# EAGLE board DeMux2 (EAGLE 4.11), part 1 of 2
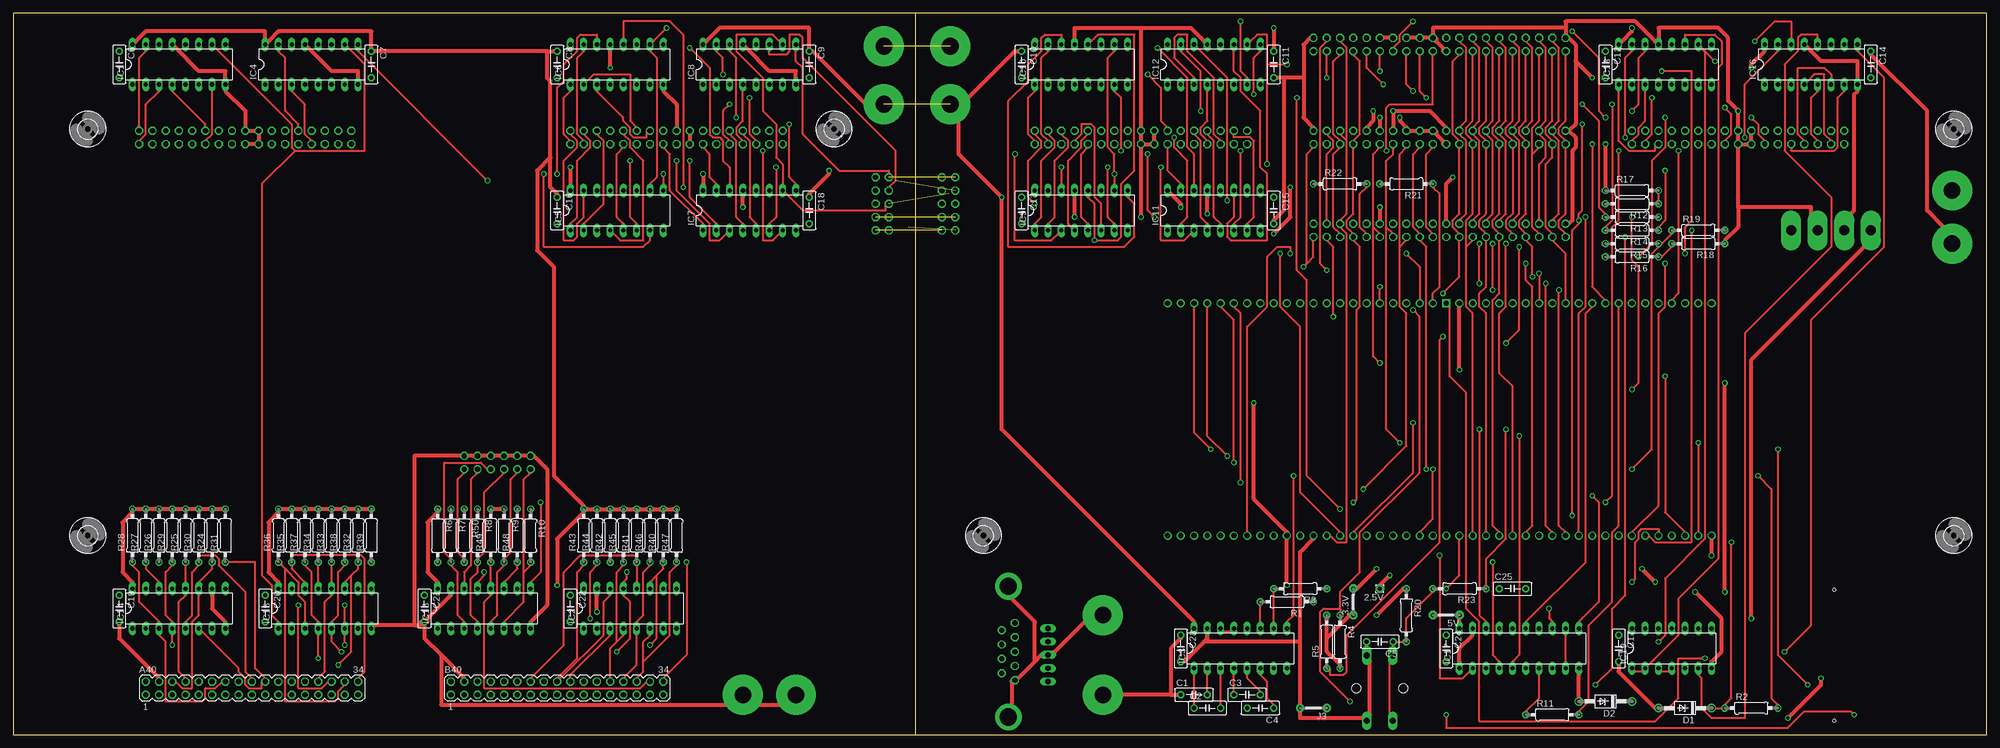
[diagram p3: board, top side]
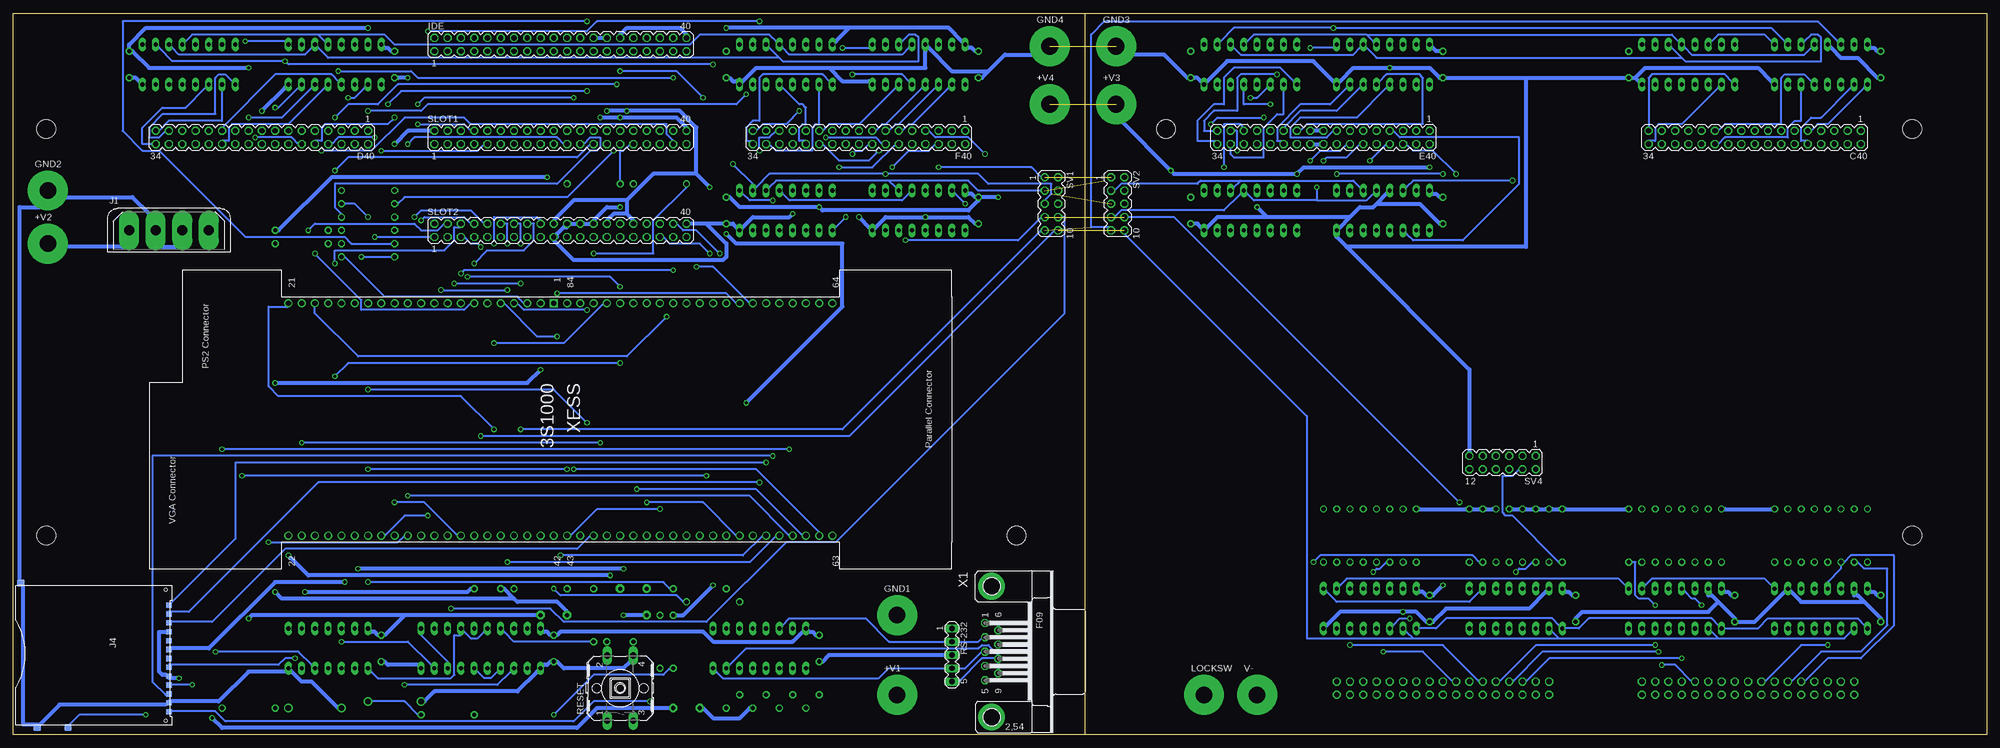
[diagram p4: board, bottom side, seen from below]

Size 377.82 x 138.11 mm. Coordinates in mm from the lower left corner, seen from the top.
Outline: 377.82,138.11 377.82,0 174.62,0 172.72,0
Outline: 377.82,138.11 173.04,138.11
Outline: 173.04,138.11 172.72,138.11
Outline: 172.72,138.11 0,138.11 0,0 172.72,0
Outline: 377.82,138.11 173.04,138.11
Outline: 172.72,138.11 172.72,0
Copper layers (1*16): Top 0.035mm / dielectric 1.5mm / Bottom 0.035mm
Design rules "15mils": minimum track width 15mil, minimum drill 24mil, track to track 15mil, track to pad 10mil, pad to pad 10mil, via to via 10mil, smd to smd 10mil, copper to edge 25mil, drill to drill 10mil, minimum pad ring 10mil, minimum via ring 8mil, stop-mask expansion 0mil, vias tented up to drill 0mil, thermal gap 10mil
Net classes: 1 supply: width 0.762 mm

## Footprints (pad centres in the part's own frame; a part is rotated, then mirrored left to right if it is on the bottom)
1,6/0,8 = drill 0.813 pad 1.6 octagon: 1 0,0
05 = drill 0.813 pad 1.6 octagon: 1 -2.54,0; 2 2.54,0
SPADELUG = drill 3.175 pad 7.62 round: 1 0,0
MA17-2 = drill 1.016 octagon: 1 -20.32,-1.27; 2 -20.32,1.27; 3 -17.78,-1.27; 4 -17.78,1.27; 5 -15.24,-1.27; 6 -15.24,1.27; 7 -12.7,-1.27; 8 -12.7,1.27; 9 -10.16,-1.27; 10 -10.16,1.27; 11 -7.62,-1.27; 12 -7.62,1.27; 13 -5.08,-1.27; 14 -5.08,1.27; 15 -2.54,-1.27; 16 -2.54,1.27; 17 0,-1.27; 18 0,1.27; 19 2.54,-1.27; 20 2.54,1.27; 21 5.08,-1.27; 22 5.08,1.27; 23 7.62,-1.27; 24 7.62,1.27; 25 10.16,-1.27; 26 10.16,1.27; 27 12.7,-1.27; 28 12.7,1.27; 29 15.24,-1.27; 30 15.24,1.27; 31 17.78,-1.27; 32 17.78,1.27; 33 20.32,-1.27; 34 20.32,1.27
C050-025X075 = drill 0.813 octagon: 1 -2.54,0; 2 2.54,0
DO41Z10 = drill 1.118 round: A 5.08,0; C -5.08,0
DIL16 = drill 0.813 long: 1 -8.89,-3.81; 2 -6.35,-3.81; 3 -3.81,-3.81; 4 -1.27,-3.81; 5 1.27,-3.81; 6 3.81,-3.81; 7 6.35,-3.81; 8 8.89,-3.81; 9 8.89,3.81; 10 6.35,3.81; 11 3.81,3.81; 12 1.27,3.81; 13 -1.27,3.81; 14 -3.81,3.81; 15 -6.35,3.81; 16 -8.89,3.81
DIL20 = drill 0.813 long: 1 -11.43,-3.81; 2 -8.89,-3.81; 3 -6.35,-3.81; 4 -3.81,-3.81; 5 -1.27,-3.81; 6 1.27,-3.81; 7 3.81,-3.81; 8 6.35,-3.81; 9 8.89,-3.81; 10 11.43,-3.81; 11 11.43,3.81; 12 8.89,3.81; 13 6.35,3.81; 14 3.81,3.81; 15 1.27,3.81; 16 -1.27,3.81; 17 -3.81,3.81; 18 -6.35,3.81; 19 -8.89,3.81; 20 -11.43,3.81
DIL14 = drill 0.813 long: 1 -7.62,-3.81; 2 -5.08,-3.81; 3 -2.54,-3.81; 4 0,-3.81; 5 2.54,-3.81; 6 5.08,-3.81; 7 7.62,-3.81; 8 7.62,3.81; 9 5.08,3.81; 10 2.54,3.81; 11 0,3.81; 12 -2.54,3.81; 13 -5.08,3.81; 14 -7.62,3.81
MA20-2 = drill 1.016 octagon: 1 -24.13,-1.27; 2 -24.13,1.27; 3 -21.59,-1.27; 4 -21.59,1.27; 5 -19.05,-1.27; 6 -19.05,1.27; 7 -16.51,-1.27; 8 -16.51,1.27; 9 -13.97,-1.27; 10 -13.97,1.27; 11 -11.43,-1.27; 12 -11.43,1.27; 13 -8.89,-1.27; 14 -8.89,1.27; 15 -6.35,-1.27; 16 -6.35,1.27; 17 -3.81,-1.27; 18 -3.81,1.27; 19 -1.27,-1.27; 20 -1.27,1.27; 21 1.27,-1.27; 22 1.27,1.27; 23 3.81,-1.27; 24 3.81,1.27; 25 6.35,-1.27; 26 6.35,1.27; 27 8.89,-1.27; 28 8.89,1.27; 29 11.43,-1.27; 30 11.43,1.27; 31 13.97,-1.27; 32 13.97,1.27; 33 16.51,-1.27; 34 16.51,1.27; 35 19.05,-1.27; 36 19.05,1.27; 37 21.59,-1.27; 38 21.59,1.27; 39 24.13,-1.27; 40 24.13,1.27
FLOPPY-4 = drill 1.93 pad 3.81 long: 1 7.62,0; 2 2.54,0; 3 -2.54,0; 4 -7.62,0
SCDA5A = smd 1 x 1.3: 1 -7.525,-0.65; 2 -5.825,-0.65; 3 -4.125,-0.65; 3A -2.425,-0.65; 4 -0.725,-0.65; 4A 0.975,-0.65; 5 2.675,-0.65; 6 4.375,-0.65; 7 6.075,-0.65; 8 7.775,-0.65; 9 -9.225,-0.65; 10 11.175,-0.65; 11 9.475,-0.65 | smd 1.4 x 1.4: 12 14.2,-19.955; 13 14.2,-25.875; 14 -13.475,-28.975 | hole 0.61: 12.875,-1.235; -12.125,-1.235
0207/10 = drill 0.813 octagon: 1 -5.08,0; 2 5.08,0
B3F-40XX = drill 1.194 long: 1 -6.248,2.489; 2 6.248,2.489; 3 -6.248,-2.489; 4 6.248,-2.489 | hole 1.803: 0,-4.496; 0,4.496
MA05-1 = drill 1.016 long: 1 -5.08,0; 2 -2.54,0; 3 0,0; 4 2.54,0; 5 5.08,0
MA05-2 = drill 1.016 octagon: 1 -5.08,-1.27; 2 -5.08,1.27; 3 -2.54,-1.27; 4 -2.54,1.27; 5 0,-1.27; 6 0,1.27; 7 2.54,-1.27; 8 2.54,1.27; 9 5.08,-1.27; 10 5.08,1.27
MA06-2 = drill 1.016 octagon: 1 -6.35,-1.27; 2 -6.35,1.27; 3 -3.81,-1.27; 4 -3.81,1.27; 5 -1.27,-1.27; 6 -1.27,1.27; 7 1.27,-1.27; 8 1.27,1.27; 9 3.81,-1.27; 10 3.81,1.27; 11 6.35,-1.27; 12 6.35,1.27
3,6 = hole 3.6: 0,0
F09HP = drill 1.016 octagon: 1 -5.486,-1.27; 2 -2.743,-1.27; 3 0,-1.27; 4 2.743,-1.27; 5 5.486,-1.27; 6 -4.115,1.27; 7 -1.372,1.27; 8 1.372,1.27; 9 4.115,1.27 | drill 3.302 pad 5.08 round: G1 -12.522,0; G2 12.522,0
3S1000 = drill 1.016 square: 1 0,0 | drill 1.016 round: 2 0,-2.54; 3 0,-5.08; 4 0,-7.62; 5 0,-10.16; 6 0,-12.7; 7 0,-15.24; 8 0,-17.78; 9 0,-20.32; 10 0,-22.86; 11 0,-25.4; 12 0,-27.94; 13 0,-30.48; 14 0,-33.02; 15 0,-35.56; 16 0,-38.1; 17 0,-40.64; 18 0,-43.18; 19 0,-45.72; 20 0,-48.26; 21 0,-50.8; 22 44.45,-50.8; 23 44.45,-48.26; 24 44.45,-45.72; 25 44.45,-43.18; 26 44.45,-40.64; 27 44.45,-38.1; 28 44.45,-35.56; 29 44.45,-33.02; 30 44.45,-30.48; 31 44.45,-27.94; 32 44.45,-25.4; 33 44.45,-22.86; 34 44.45,-20.32; 35 44.45,-17.78; 36 44.45,-15.24; 37 44.45,-12.7; 38 44.45,-10.16; 39 44.45,-7.62; 40 44.45,-5.08; 41 44.45,-2.54; 42 44.45,0; 43 44.45,2.54; 44 44.45,5.08; 45 44.45,7.62; 46 44.45,10.16; 47 44.45,12.7; 48 44.45,15.24; 49 44.45,17.78; 50 44.45,20.32; 51 44.45,22.86; 52 44.45,25.4; 53 44.45,27.94; 54 44.45,30.48; 55 44.45,33.02; 56 44.45,35.56; 57 44.45,38.1; 58 44.45,40.64; 59 44.45,43.18; 60 44.45,45.72; 61 44.45,48.26; 62 44.45,50.8; 63 44.45,53.34; 64 0,53.34; 65 0,50.8; 66 0,48.26; 67 0,45.72; 68 0,43.18; 69 0,40.64; 70 0,38.1; 71 0,35.56; 72 0,33.02; 73 0,30.48; 74 0,27.94; 75 0,25.4; 76 0,22.86; 77 0,20.32; 78 0,17.78; 79 0,15.24; 80 0,12.7; 81 0,10.16; 82 0,7.62; 83 0,5.08; 84 0,2.54

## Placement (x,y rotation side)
2.5V  [1,6/0,8]  261.62,27.94 180 top
3.3V  J5MM  [05]  256.54,25.4 90 top
5V  J5MM  [05]  274.32,22.86 180 top
+V1  LUG  [SPADELUG]  208.6,7.62 0 bottom
+V2  LUG  [SPADELUG]  371.16,93.98 0 bottom
+V3  LUG  [SPADELUG]  166.69,120.65 0 bottom
+V4  LUG  [SPADELUG]  179.39,120.65 0 bottom
A40  [MA17-2]  45.72,8.89 0 top
B40  [MA17-2]  104.14,8.89 0 top
C1  0.1uf  [C050-025X075]  226.06,7.62 0 top
C2  0.1uf  [C050-025X075]  228.6,5.08 0 top
C3  0.1uf  [C050-025X075]  236.22,7.62 0 top
C4  0.1uf  [C050-025X075]  238.76,5.08 180 top
C5  0.1uf  [C050-025X075]  261.62,17.78 180 top
C6  0.1uf  [C050-025X075]  20.32,128.27 270 top
C7  0.1uf  [C050-025X075]  68.58,128.27 270 top
C8  0.1uf  [C050-025X075]  104.14,128.27 270 top
C9  0.1uf  [C050-025X075]  152.4,128.27 270 top
C10  0.1uf  [C050-025X075]  193.04,128.27 270 top
C11  0.1uf  [C050-025X075]  241.3,128.27 270 top
C12  0.1uf  [C050-025X075]  304.8,128.27 270 top
C13  0.1uf  [C050-025X075]  193.04,100.33 270 top
C14  0.1uf  [C050-025X075]  355.6,128.27 270 top
C15  0.1uf  [C050-025X075]  241.3,100.33 270 top
C16  0.1uf  [C050-025X075]  104.14,100.33 270 top
C17  0.1uf  [C050-025X075]  307.34,16.51 270 top
C18  0.1uf  [C050-025X075]  152.4,100.33 270 top
C19  0.1uf  [C050-025X075]  20.32,24.13 270 top
C20  0.1uf  [C050-025X075]  48.26,24.13 270 top
C21  0.1uf  [C050-025X075]  78.74,24.13 270 top
C22  0.1uf  [C050-025X075]  106.68,24.13 270 top
C23  0.1uf  [C050-025X075]  223.52,16.51 270 top
C24  0.1uf  [C050-025X075]  274.32,16.51 270 top
C25  0.1uf  [C050-025X075]  287.02,27.94 0 top
C40  [MA17-2]  44.45,114.3 180 bottom
D1  1N4728  [DO41Z10]  320.04,5.08 180 top
D2  1N4728  [DO41Z10]  304.8,6.35 180 top
D40  [MA17-2]  330.2,114.3 180 bottom
E40  [MA17-2]  127,114.3 180 bottom
F40  [MA17-2]  215.9,114.3 180 bottom
GND1  LUG  [SPADELUG]  208.6,22.86 0 bottom
GND2  LUG  [SPADELUG]  371.16,104.14 0 bottom
GND3  LUG  [SPADELUG]  166.69,131.76 0 bottom
GND4  LUG  [SPADELUG]  179.39,131.76 0 bottom
IC1  74HC595N  [DIL16]  31.75,128.27 0 top
IC2  74HC165N  [DIL16]  118.11,24.13 0 top
IC3  MAX232  [DIL16]  234.95,16.51 0 top
IC4  74HC595N  [DIL16]  57.15,128.27 0 top
IC5  74HC595N  [DIL16]  115.57,100.33 0 top
IC6  74HC595N  [DIL16]  115.57,128.27 0 top
IC7  74HC595N  [DIL16]  140.97,100.33 0 top
IC8  74HC595N  [DIL16]  140.97,128.27 0 top
IC9  74HC595N  [DIL16]  204.47,100.33 0 top
IC10  74HC595N  [DIL16]  204.47,128.27 0 top
IC11  74HC595N  [DIL16]  229.87,100.33 0 top
IC12  74HC595N  [DIL16]  229.87,128.27 0 top
IC13  74HC595N  [DIL16]  316.23,128.27 0 top
IC14  74HC165N  [DIL16]  31.75,24.13 0 top
IC15  74HC165N  [DIL16]  59.69,24.13 0 top
IC16  74HC595N  [DIL16]  344.17,128.27 0 top
IC17  74HCT244N  [DIL20]  288.29,16.51 0 top
IC18  74HC165N  [DIL16]  90.17,24.13 0 top
IC19  74ALS00N  [DIL14]  317.5,16.51 0 top
IDE  [MA20-2]  273.05,132.08 0 bottom
J1  [FLOPPY-4]  347.98,96.52 0 bottom
J3  J5MM  [05]  248.92,5.08 180 top
J4  SDCARD  [SCDA5A]  347.35,15.56 270 bottom
LOCKSW  LUG  [SPADELUG]  149.86,7.62 0 bottom
R1  330  [0207/10]  243.84,25.4 180 top
R2  330  [0207/10]  332.74,5.08 0 top
R3  330  [0207/10]  246.38,27.94 180 top
R4  330  [0207/10]  254,17.78 270 top
R5  330  [0207/10]  251.46,17.78 90 top
R6  3K  [0207/10]  81.28,38.1 270 top
R7  3K  [0207/10]  83.82,38.1 270 top
R8  3K  [0207/10]  88.9,38.1 270 top
R9  3K  [0207/10]  93.98,38.1 270 top
R10  3K  [0207/10]  99.06,38.1 270 top
R11  330  [0207/10]  294.64,3.81 0 top
R12  330  [0207/10]  309.88,101.6 180 top
R13  47  [0207/10]  309.88,99.06 180 top
R14  47  [0207/10]  309.88,96.52 180 top
R15  330  [0207/10]  309.88,93.98 180 top
R16  330  [0207/10]  309.88,91.44 180 top
R17  10K  [0207/10]  309.88,104.14 0 top
R18  10K  [0207/10]  322.58,93.98 180 top
R19  10K  [0207/10]  322.58,96.52 0 top
R20  4.7K  [0207/10]  266.7,22.86 270 top
R21  330  [0207/10]  266.7,105.41 180 top
R22  330  [0207/10]  254,105.41 0 top
R23  330  [0207/10]  276.86,27.94 180 top
R24  3K  [0207/10]  38.1,38.1 90 top
R25  3K  [0207/10]  33.02,38.1 90 top
R26  3K  [0207/10]  27.94,38.1 90 top
R27  3K  [0207/10]  25.4,38.1 90 top
R28  3K  [0207/10]  22.86,38.1 90 top
R29  3K  [0207/10]  30.48,38.1 90 top
R30  3K  [0207/10]  35.56,38.1 90 top
R31  3K  [0207/10]  40.64,38.1 90 top
R32  3K  [0207/10]  66.04,38.1 90 top
R33  3K  [0207/10]  60.96,38.1 90 top
R34  3K  [0207/10]  58.42,38.1 90 top
R35  3K  [0207/10]  53.34,38.1 90 top
R36  3K  [0207/10]  50.8,38.1 90 top
R37  3K  [0207/10]  55.88,38.1 90 top
R38  3K  [0207/10]  63.5,38.1 90 top
R39  3K  [0207/10]  68.58,38.1 90 top
R40  3K  [0207/10]  124.46,38.1 90 top
R41  3K  [0207/10]  119.38,38.1 90 top
R42  3K  [0207/10]  114.3,38.1 90 top
R43  3K  [0207/10]  109.22,38.1 90 top
R44  3K  [0207/10]  111.76,38.1 90 top
R45  3K  [0207/10]  116.84,38.1 90 top
R46  3K  [0207/10]  121.92,38.1 90 top
R47  3K  [0207/10]  127,38.1 90 top
R48  3K  [0207/10]  96.52,38.1 90 top
R49  3K  [0207/10]  91.44,38.1 90 top
R50  3K  [0207/10]  86.36,38.1 270 top
RESET  [B3F-40XX]  261.62,8.89 90 bottom
RS-232  [MA05-1]  198.12,15.24 270 bottom
SLOT1  [MA20-2]  273.05,114.3 0 bottom
SLOT2  [MA20-2]  273.05,96.52 0 bottom
SV1  [MA05-2]  179.07,101.6 270 bottom
SV2  [MA05-2]  166.37,101.6 270 bottom
SV4  [MA06-2]  92.71,52.07 180 bottom
U$5  [3,6]  371.48,115.89 0 top
U$6  [3,6]  371.48,38.1 0 top
U$7  [3,6]  185.74,38.1 0 top
U$8  [3,6]  14.29,38.1 0 top
U$9  [3,6]  14.29,115.89 0 top
U$11  [3,6]  157.16,115.89 0 top
V-  LUG  [SPADELUG]  139.7,7.62 0 bottom
X1  [F09HP]  190.5,15.88 270 bottom
XESS  3S1000  [3S1000]  274.32,82.55 270 bottom

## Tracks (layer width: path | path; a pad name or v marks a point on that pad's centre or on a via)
3S-LSCK  (via drill 0.61)
  Top 0.381: v283.21,33.02 283.21,15.24 284.48,13.97 IC17.4
  Bottom 0.381: IC17.4 285.12,12.06 286.38,10.79 287.65,10.79 288.93,12.06 IC17.6 | v283.21,33.02 236.85,33.02 231.78,38.1 XESS.59
3S-LSER  (via drill 0.61)
  Top 0.381: v273.05,34.29 273.05,10.79 277.5,10.79 278.76,12.06 IC17.2
  Bottom 0.381: v273.05,34.29 238.12,34.29 234.31,38.1 XESS.58
3S-SCL\  (via drill 0.61)
  Top 0.381: v302.26,45.72 303.53,44.45 303.53,25.4 299.72,21.59 IC17.11
  Bottom 0.381: IC17.8 294.64,13.97 299.72,19.05 IC17.11 | v302.26,45.72 236.85,45.72 229.24,38.1 XESS.60
3S-SCLK
  Top 0.381: IC17.15 289.56,21.59 300.99,33.02 300.99,80.64 302.26,81.92 XESS.12
3S-SSER
  Top 0.381: XESS.14 307.34,81.92 307.34,40.01 306.07,38.73 306.07,25.4 301.62,20.95 301.62,6.35 299.72,4.45 R11.2
  Bottom 0.381: R11.2 300.36,3.81 302.89,6.35 309.25,6.35 D2.C
+2V5  (via drill 0.61)
  Top 0.762: v325.12,34.29 325.12,37.47 XESS.22 | v263.52,30.48 261.62,28.57 2.5V.1
  Bottom 0.762: v325.12,34.29 321.31,30.48 v263.52,30.48
+3V3  (via drill 0.61)
  Top 0.762: v260.99,22.86 266.06,27.94 R20.1 | 251.46,18.41 251.46,22.23 R5.2 | 251.46,18.41 251.46,15.88 254,13.34 R4.2 | v243.84,28.57 243.84,37.47 XESS.54 243.84,38.73 237.49,45.09 v237.49,63.5 | 251.46,18.41 255.91,22.86 3.3V.1 | v260.35,119.38 260.35,117.47 259.08,116.2 SLOT1.32 | SLOT1.28 264.16,116.2 v264.16,119.38 271.14,119.38 274.32,116.2 SLOT1.20 | v275.59,106.68 274.32,105.41 274.32,98.42 SLOT2.20 | v241.3,95.89 244.47,99.06 v244.47,104.78
  Bottom 0.762: v260.99,22.86 257.18,22.86 3.3V.1 | v243.84,28.57 249.56,22.86 250.82,22.86 R5.2 | v264.16,119.38 v260.35,119.38 250.19,119.38 247.01,116.2 247.01,107.31 | 260.35,99.69 259.08,98.42 SLOT2.32 | 260.35,99.69 262.89,99.69 264.16,98.42 SLOT2.28 | v275.59,106.68 316.87,106.68 327.02,96.52 R19.2 | 260.35,102.23 260.35,99.69 | 260.35,102.23 270.51,102.23 274.32,98.42 SLOT2.20 | 247.01,107.31 255.27,107.31 260.35,102.23 | v237.49,63.5 219.07,81.92 219.07,93.98 239.4,93.98 v241.3,95.89 | v244.47,104.78 247.01,107.31
+5V  (via drill 0.61)
  Top 0.762: v276.86,69.85 276.86,81.92 XESS.2 | v327.66,27.3 v327.66,67.31
  Bottom 0.762: 281.94,26.04 281.31,25.4 273.69,25.4 271.78,23.5 5V.2 | 281.94,26.04 283.85,27.94 C25.1 | v276.86,69.85 279.4,67.31 v327.66,67.31 | v327.66,27.3 326.39,26.04 281.94,26.04
AC0
  Bottom 0.381: IC5.3 111.12,95.89 109.86,94.61 100.33,94.61 89.53,105.41 89.53,114.3 112.39,114.3 113.67,115.57 E40.7
AC1
  Top 0.381: IC6.15 109.22,130.81 107.95,129.54 107.95,114.94 109.22,113.67 E40.4
AC2
  Bottom 0.381: IC6.5 116.2,125.09 114.94,126.36 108.58,126.36 107.95,125.73 107.95,116.84 130.18,116.84 131.44,115.57 E40.21
AC3  (via drill 0.61)
  Top 0.381: v129.54,109.86 129.54,102.87 134.62,97.79 IC7.2
  Bottom 0.381: v129.54,109.86 127.64,111.76 123.83,111.76 122.56,113.03 E40.14
AC4  (via drill 0.61)
  Top 0.381: v143.51,111.76 143.51,94.61 145.41,94.61 146.69,95.89 IC7.7
  Bottom 0.381: v143.51,111.76 143.51,115.57 144.15,115.57 E40.31
AC5
  Top 0.381: IC8.4 139.7,123.19 139.7,117.47 138.43,116.2 138.43,114.94 139.7,113.67 E40.28
AC6  (via drill 0.61)
  Top 0.381: v191.77,111.12 191.77,94.61 198.75,94.61 200.03,95.89 IC9.3
  Bottom 0.381: v191.77,111.12 194.94,114.3 201.29,114.3 202.56,115.57 F40.7
AC7
  Top 0.381: IC10.15 198.12,130.81 196.85,129.54 196.85,114.94 198.12,113.67 F40.4
AC8  (via drill 0.61)
  Top 0.381: v217.17,126.36 219.71,123.83 219.71,117.47 220.98,116.2 F40.21
  Bottom 0.381: v217.17,126.36 207.65,126.36 206.38,125.09 IC10.5
AC9  (via drill 0.61)
  Top 0.381: v222.25,114.3 222.25,112.39 224.79,109.86 224.79,99.06 223.52,97.79 IC11.2
  Bottom 0.381: v222.25,114.3 212.72,114.3 211.46,113.03 F40.14
AC10
  Top 0.381: IC11.7 236.22,97.79 237.49,99.06 237.49,113.67 236.85,114.3 233.68,114.3 233.68,114.94 F40.31
AC11
  Top 0.381: IC12.4 228.6,123.19 228.6,117.47 227.33,116.2 227.33,114.94 228.6,113.67 F40.28
AND
  Top 0.381: IC13.3 312.42,123.19 312.42,117.47 311.15,116.2 311.15,114.94 309.88,113.67 D40.2
BREAK  (via drill 0.61)
  Top 0.381: v332.74,118.11 334.01,116.84 334.01,114.94 335.28,113.67 D40.22
  Bottom 0.381: v332.74,118.11 326.39,118.11 320.68,123.83 IC13.6
CA
  Top 0.381: IC16.4 343.54,125.09 344.81,126.36 346.71,126.36 346.71,114.94 347.98,113.67 D40.32
CF1  (via drill 0.61)
  Top 0.381: v90.17,31.11 90.17,30.48 88.9,29.21 IC18.13 | SV4.2 86.36,50.16 85.09,48.9 85.09,34.92 86.36,33.66 R50.2
  Bottom 0.381: v90.17,31.11 89.53,31.75 88.27,31.75 87,33.02 R50.2
CF2
  Top 0.381: IC18.14 86.36,29.21 86.36,31.11 87.63,32.38 87.63,48.9 88.9,50.16 SV4.4
  Bottom 0.381: R6.2 81.92,33.02 90.81,41.91 92.08,41.91 92.71,42.55 92.71,49.53 90.81,49.53 89.53,50.8 SV4.4
CF3
  Top 0.381: IC18.3 86.36,21.59 85.09,22.86 85.09,31.11 83.82,32.38 R7.2 83.82,33.66 82.55,34.92 82.55,52.07 89.53,52.07 90.81,50.8 SV4.6
CF4
  Top 0.381: IC18.4 88.9,21.59 87.63,22.86 87.63,29.84 88.9,31.11 88.9,32.38 R8.2 88.9,33.66 90.17,34.92 90.17,46.35 93.98,50.16 SV4.8
CF5
  Top 0.381: IC18.5 91.44,21.59 92.71,22.86 92.71,31.11 93.98,32.38 R9.2 93.98,33.66 95.25,34.92 95.25,48.9 96.52,50.16 SV4.10
CF6
  Top 0.381: 97.79,31.11 97.79,25.4 93.98,21.59 IC18.6 | 97.79,31.11 99.06,32.38 R10.2 | 97.79,31.11 97.79,48.9 99.06,50.16 SV4.12
CLK  (via drill 0.61)
  Top 0.381: SLOT2.21 271.78,95.89 270.51,97.16 270.51,111.12 271.78,112.39 SLOT1.21 | v302.26,113.03 302.26,85.72 304.8,83.19 XESS.13
  Bottom 0.381: v302.26,113.03 300.99,114.3 273.69,114.3 272.42,113.03 SLOT1.21
CONT
  Top 0.381: B40.28 116.84,10.79 119.38,13.34 119.38,19.05 IC2.5 119.38,21.59 120.65,22.86 120.65,31.11 121.92,32.38 R46.1
DCA  (via drill 0.61)
  Top 0.381: v308.61,114.3 308.61,129.54 309.88,130.81 IC13.15
  Bottom 0.381: v308.61,114.3 315.6,114.3 316.87,113.03 D40.8
DEFER
  Top 0.381: IC16.7 350.52,123.19 349.25,121.92 349.25,112.39 348.62,111.76 340.36,111.76 340.36,112.39 D40.26
DEP  (via drill 0.61)
  Top 0.381: IC2.3 114.3,19.05 106.68,11.43 106.68,10.79 B40.20 | v110.49,22.23 110.49,31.11 111.76,32.38 R44.1
  Bottom 0.381: v110.49,22.23 112.39,22.23 113.67,20.95 IC2.3
DF0
  Top 0.381: IC1.15 25.4,130.81 24.13,129.54 24.13,116.2 C40.1
DF1
  Bottom 0.381: IC1.2 26.04,123.83 31.75,118.11 33.66,118.11 35.56,116.2 35.56,113.67 34.29,113.67 C40.10
DF2
  Top 0.381: IC1.4 30.48,123.19 36.83,116.84 36.83,116.2 C40.11
EXAM
  Top 0.381: 115.57,17.78 114.3,16.51 114.3,10.79 B40.26 | 115.57,17.78 116.84,19.05 IC2.4 | 115.57,17.78 115.57,31.11 116.84,32.38 R45.1
EXECUTE
  Top 0.381: IC16.6 347.98,125.73 347.98,126.36 346.71,127.64 341.63,127.64 341.63,114.94 342.9,113.67 D40.28
FETCH
  Bottom 0.381: IC13.5 318.13,123.83 325.12,116.84 335.92,116.84 336.55,116.2 336.55,113.67 337.82,113.67 D40.24
GND  (via drill 0.61)  (1 unrouted)
  Top 0.762: IC8.13 140.34,131.44 144.78,127 149.86,127 149.86,125.73 IC8.8 | C40.18 45.09,113.03 46.35,113.03 C40.20 46.99,113.67 46.99,114.94 C40.19 46.35,115.57 45.09,115.57 C40.17 44.45,116.2 44.45,119.38 40.64,123.19 IC1.8 40.64,125.73 40.64,127 35.56,127 31.11,131.44 IC1.13 | IC4.13 56.52,131.44 60.96,127 66.04,127 66.04,125.73 IC4.8 | E40.19 129.54,114.94 129.54,113.67 E40.20 | IC6.8 124.46,123.19 127,120.65 127,116.2 E40.17 | v114.3,127.64 114.3,130.81 IC6.13 | v139.7,100.97 139.7,102.87 IC7.13 | IC14.8 40.64,21.59 38.1,24.13 38.1,26.67 IC14.10 | A40.4 27.94,10.79 20.32,18.41 20.32,20.95 C19.2 | LOCKSW.1 146.69,5.71 142.88,5.71 V-.1 136.53,5.71 81.92,5.71 81.92,15.24 | IC18.8 99.06,21.59 102.23,24.77 102.23,50.8 99.69,53.34 SV4.11 98.42,53.34 97.16,53.34 SV4.9 95.89,53.34 94.61,53.34 SV4.7 93.34,53.34 92.08,53.34 SV4.5 90.81,53.34 89.53,53.34 SV4.3 88.27,53.34 87,53.34 SV4.1 85.72,53.34 76.83,53.34 76.83,20.95 | v111.76,23.5 111.76,26.67 IC2.15 | 76.83,20.95 78.11,20.95 78.11,21.59 C21.2 | 76.83,20.95 69.22,20.95 IC15.8 | IC18.15 83.82,26.67 79.38,22.23 79.38,21.59 C21.2 | 81.92,15.24 78.74,18.41 78.74,20.95 C21.2 | 81.92,15.24 86.36,10.79 B40.4 | IC17.10 299.72,11.43 299.72,6.99 D2.A | D1.A 314.32,5.08 307.34,12.06 307.34,13.34 C17.2 | v321.94,27.3 327.02,22.23 327.02,15.88 325.12,13.97 IC19.7 | IC17.19 279.4,19.05 276.86,16.51 276.86,13.97 IC17.1 | C5.2 259.08,17.14 259.08,16.51 RESET.4 259.71,13.97 259.71,3.81 RESET.3 258.44,3.17 246.38,3.17 246.38,4.45 J3.2 246.38,5.71 246.38,17.78 | 246.38,17.78 246.38,34.92 248.92,37.47 XESS.52 | 227.97,17.78 228.6,18.41 228.6,19.05 IC3.15
  Top 0.762: 227.97,17.78 224.16,13.97 C23.2 | X1.G2 191.13,5.71 191.13,10.16 X1.5 192.41,10.79 195.58,13.97 | 195.58,13.97 196.85,15.24 RS-232.3 199.39,15.24 199.39,15.88 205.1,21.59 GND1.1 | 195.58,13.97 195.58,21.59 191.13,26.04 X1.G1 | 246.38,17.78 227.97,17.78 | v203.2,99.06 203.2,102.87 IC9.13 | F40.18 216.53,113.03 217.81,113.03 F40.20 218.44,113.67 218.44,114.94 F40.19 | F40.18 215.9,113.67 215.9,114.94 F40.17 215.9,116.2 215.9,135.25 | 215.9,135.25 203.2,135.25 203.2,133.35 IC10.13 | 215.9,135.25 225.43,135.25 227.97,132.72 IC12.13 | v215.9,99.06 215.9,112.39 F40.18 | 330.2,100.97 330.2,112.39 D40.18 | 330.2,100.97 330.2,97.16 327.66,94.61 R18.1 | D40.18 330.83,113.03 332.11,113.03 D40.20 332.74,113.67 332.74,114.94 D40.19 | D40.18 330.2,113.67 330.2,114.94 D40.17 330.2,116.2 v330.2,119.38 328.3,121.28 328.3,133.35 326.39,135.25 314.96,135.25 314.96,133.35 IC13.13 314.32,132.72 310.51,136.53 297.18,136.53 297.18,135.25 | IC16.13 343.54,131.44 346.07,128.91 353.06,128.91 353.06,125.73 IC16.8 353.06,123.19 352.43,122.56 352.43,100.33 351.79,99.69 J1.3 | 330.2,100.97 344.17,100.97 344.17,99.69 J1.2 | v261.62,100.97 261.62,98.42 SLOT2.30 | v228.6,99.69 228.6,102.87 IC11.13 | v304.8,113.03 304.8,104.78 R17.1 | 297.81,115.57 299.08,114.3 299.08,112.39 298.45,111.76 298.45,98.42 297.81,97.79 SLOT2.2 | 297.81,115.57 SLOT1.2 297.81,115.57 | 299.08,128.91 v302.26,125.73 | 299.08,128.91 299.08,132.08 297.81,133.35 IDE.2 297.18,133.99 297.18,135.25 | 297.81,115.57 299.08,116.84 299.08,128.91 | IDE.30 262.25,133.35 263.52,133.35 IDE.28 | IDE.26 267.33,133.35 268.61,133.35 IDE.24 269.88,133.35 271.14,133.35 IDE.22
  Top 0.762: IDE.19 273.69,130.81 273.69,131.44 272.42,132.72 272.42,133.35 IDE.22 | SLOT1.19 273.69,113.03 273.69,113.67 272.42,114.94 272.42,115.57 SLOT1.22 271.14,115.57 269.88,115.57 SLOT1.24 268.61,115.57 267.33,115.57 SLOT1.26 266.7,116.2 265.43,117.47 v265.43,118.11 | 247.01,125.73 247.01,132.08 248.28,133.35 IDE.40 | 247.01,125.73 247.01,118.11 248.92,116.2 SLOT1.40 | v261.62,118.11 261.62,116.2 SLOT1.30 | 247.01,125.73 243.21,125.73 | 243.21,125.73 241.94,125.73 C11.2 | 297.18,135.25 271.78,135.25 271.78,133.99 IDE.22 | 243.21,125.73 243.21,100.33 241.3,98.42 C15.2
  Bottom 0.762: GND3.1 163.19,130.18 157.48,130.18 153.03,125.73 C9.2 151.76,125.73 151.13,125.73 150.5,125.09 IC8.8 149.22,125.09 145.41,128.91 128.91,128.91 125.09,125.09 IC6.8 123.83,125.09 121.28,127.64 v114.3,127.64 106.68,127.64 104.78,125.73 C8.2 103.5,125.73 88.27,125.73 | C6.2 20.95,125.73 24.77,129.54 27.94,129.54 29.84,131.44 IC1.13 | 67.31,125.73 66.67,125.09 IC4.8 | 67.31,125.73 67.94,125.73 C7.2 69.22,125.73 88.27,125.73 | E40.18 127.64,113.03 128.91,113.03 E40.20 | E40.19 128.91,115.57 127.64,115.57 E40.17 | 67.31,125.73 65.41,127.64 43.81,127.64 41.27,125.09 IC1.8 | C18.2 151.76,97.79 151.13,97.79 150.5,97.16 IC7.8 149.22,97.16 147.32,99.06 137.79,99.06 | 121.92,99.06 120.02,100.97 117.47,100.97 116.84,101.6 | 121.92,99.06 123.83,97.16 IC5.8 124.46,95.25 122.56,93.34 | 116.84,101.6 114.94,103.5 IC5.13 | 116.84,101.6 108.58,101.6 104.78,97.79 C16.2 | 137.79,99.06 v139.7,100.97 | 121.92,99.06 137.79,99.06 | 51.44,25.4 52.7,26.67 53.34,26.67 IC15.15 | 51.44,25.4 48.26,22.23 C20.2 47.62,21.59 44.45,21.59 38.73,27.3 IC14.10 37.47,27.3 35.56,25.4 23.5,25.4 | 23.5,25.4 24.77,26.67 25.4,26.67 IC14.15 | 23.5,25.4 20.32,22.23 C19.2 | IC2.8 126.36,20.95 123.83,23.5 v111.76,23.5 109.22,23.5 107.31,21.59 C22.2 106.05,21.59 103.5,24.13 87.63,24.13 84.45,27.3 IC18.15 | 51.44,25.4 53.34,23.5 77.47,23.5 78.74,22.23 C21.2 | 122.56,93.34 99.06,69.85 99.06,53.98 SV4.11 | 88.27,125.73 88.27,93.34 122.56,93.34 | C17.2 306.7,13.97 306.07,13.34 300.36,13.34 IC17.10 | v321.94,27.3 290.83,27.3 290.19,27.94 C25.2 | D1.A 315.6,5.08 320.68,10.16 322.58,10.16 324.49,12.06 IC19.7 325.75,12.06 332.74,12.06 338.45,6.35 347.98,6.35 J4.11 348.62,5.71 368.94,5.71 372.75,1.91 J4.13 373.38,1.91 375.92,1.91 375.92,28.57 J4.14 376.56,29.21 376.56,100.97 372.75,100.97 GND2.1 367.67,102.87 354.96,102.87 351.79,99.69 J1.3 349.25,93.34 346.71,93.34 J1.2
  Bottom 0.762: RESET.4 259.71,13.97 260.99,12.7 272.42,12.7 273.69,13.97 C24.2 274.95,13.97 275.59,13.34 276.23,13.34 IC17.1 277.5,12.06 281.31,8.26 297.18,8.26 299.08,6.35 D2.A | C4.2 236.85,5.08 238.76,3.17 243.84,3.17 245.75,5.08 J3.2 | C23.2 222.88,13.97 221.62,15.24 199.39,15.24 RS-232.3 | C13.2 193.68,97.79 194.94,99.06 v203.2,99.06 210.82,99.06 212.72,97.16 IC9.8 214,97.16 v215.9,99.06 | 191.13,127 187.96,130.18 182.88,130.18 GND4.1 | 191.13,127 192.41,125.73 C10.2 | 191.13,127 198.12,127 202.56,131.44 IC10.13 203.2,130.81 203.2,127.64 221.62,127.64 | v330.2,119.38 325.75,123.83 IC13.8 | IC16.8 353.69,125.09 354.33,125.73 354.96,125.73 C14.2 | v261.62,100.97 264.16,100.97 266.7,98.42 SLOT2.26 267.33,97.79 268.61,97.79 SLOT2.24 269.88,97.79 271.14,97.79 SLOT2.22 271.78,97.16 272.42,97.16 273.69,95.89 273.69,95.25 SLOT2.19 274.32,94.61 270.51,90.81 241.94,90.81 241.3,91.44 241.3,93.98 245.11,97.79 | v228.6,99.69 229.24,99.06 236.22,99.06 238.12,97.16 IC11.8 239.4,97.16 240.03,97.79 240.66,97.79 C15.2 241.94,97.79 245.11,97.79 | 245.11,97.79 248.28,97.79 SLOT2.40 | v304.8,113.03 302.26,115.57 297.81,115.57 SLOT1.2 | v302.26,125.73 304.17,125.73 C12.2 | 221.62,127.64 219.07,125.09 214,125.09 IC10.8 | 221.62,127.64 235.59,127.64 238.12,125.09 IC12.8 239.4,125.09 240.03,125.09 240.66,125.73 C11.2 | IDE.26 266.06,133.35 264.8,133.35 IDE.28 | SLOT1.40 248.92,116.2 250.82,118.11 v261.62,118.11 v265.43,118.11 | IDE.30 261.62,133.99 260.35,135.25 250.19,135.25 248.92,133.99 IDE.40
I2C-SCL  (via drill 0.61)
  Top 0.381: 262.89,97.16 264.16,95.89 SLOT2.27 | 262.89,97.16 262.89,109.86 264.16,111.12 264.16,112.39 SLOT1.27 | v322.58,55.88 322.58,38.73 XESS.23 | v265.43,55.88 262.89,58.42 262.89,97.16
  Bottom 0.381: v265.43,55.88 v322.58,55.88
I2C-SDA  (via drill 0.61)
  Top 0.381: 260.35,97.16 261.62,95.89 SLOT2.29 | 260.35,97.16 260.35,111.12 261.62,112.39 SLOT1.29 | v316.23,68.58 316.23,42.55 320.04,38.73 XESS.24 | v261.62,71.12 260.35,72.39 260.35,97.16
  Bottom 0.381: v316.23,68.58 313.69,71.12 v261.62,71.12
IDE-CS0#  (via drill 0.61)
  Top 0.381: v251.46,125.73 251.46,130.18 IDE.37 | v315.6,127 321.31,127 321.31,98.42 320.04,97.16 v320.04,92.08
  Bottom 0.381: v251.46,125.73 300.36,125.73 301.62,127 v315.6,127 | v320.04,92.08 311.15,83.19 311.15,81.28 291.46,81.28 290.19,82.55 XESS.7
IDE-CS1#  (via drill 0.61)
  Top 0.381: v292.1,88.27 292.1,83.19 XESS.8 | v251.46,88.9 250.19,90.17 250.19,131.44 251.46,132.72 IDE.38
  Bottom 0.381: v292.1,88.27 291.46,88.9 v251.46,88.9
IDE-DMACK#  (via drill 0.61)
  Top 0.381: v254,43.18 247.65,49.53 247.65,87 245.75,88.9 v245.75,121.92 | v261.62,127 261.62,130.18 IDE.29
  Bottom 0.381: v254,43.18 266.06,43.18 271.14,38.1 XESS.43 | v245.75,121.92 250.82,127 v261.62,127
IDE-DMARQ  (via drill 0.61)
  Top 0.381: R12.1 314.96,102.23 314.96,103.5 R17.2 | v267.97,59.69 267.97,50.16 256.54,38.73 XESS.49 | v309.88,66.04 311.15,67.31 311.15,89.53 309.88,90.81 v309.88,99.06
  Bottom 0.381: v267.97,59.69 274.32,66.04 v309.88,66.04 | v309.88,99.06 312.42,101.6 314.32,101.6 R12.1
IDE-IORDY  (via drill 0.61)
  Top 0.381: R19.1 317.5,95.89 315.6,93.98 R15.1 314.96,93.34 313.69,92.08 313.69,54.61 v309.88,50.8 | v271.78,50.8 271.78,41.27 269.24,38.73 XESS.44
  Bottom 0.381: v271.78,50.8 v309.88,50.8
IDE-IRQ
  Top 0.381: R16.1 315.6,91.44 317.5,93.34 R18.2
  Bottom 0.381: XESS.3 280.04,82.55 281.31,83.82 306.7,83.82 314.32,91.44 R16.1
IF0
  Bottom 0.381: IC1.6 35.56,123.19 35.56,117.47 36.83,117.47 38.1,116.2 38.1,114.3 50.16,114.3 51.44,113.03 C40.24
IF1
  Top 0.381: IC4.15 50.8,130.81 52.07,129.54 52.07,119.38 54.61,116.84 54.61,116.2 C40.25
IF2
  Bottom 0.381: IC4.2 51.44,123.83 58.42,116.84 62.87,116.84 63.5,116.2 63.5,113.67 64.77,113.67 C40.34
ION
  Bottom 0.381: IC16.3 341,123.83 344.81,120.02 349.25,120.02 353.06,116.2 353.06,113.03 351.15,113.03 D40.34
IOT
  Bottom 0.381: IC13.4 315.6,125.09 316.87,126.36 327.66,126.36 337.82,116.2 D40.23
ISZ
  Top 0.381: IC13.1 307.34,123.19 307.34,113.67 309.25,111.76 314.32,111.76 314.32,113.03 D40.6
JMP  (via drill 0.61)
  Top 0.381: v331.47,114.3 331.47,124.46 337.82,130.81 IC16.15
  Bottom 0.381: v331.47,114.3 324.49,114.3 323.21,113.03 D40.12
JMS  (via drill 0.61)
  Top 0.381: v234.95,136.53 234.95,127 236.22,125.73 IC12.7 | v298.45,134.62 303.53,129.54 303.53,119.38 v304.8,118.11
  Bottom 0.381: v234.95,136.53 266.06,136.53 267.97,134.62 v298.45,134.62 | v304.8,118.11 306.07,116.84 318.13,116.84 318.77,116.2 318.77,113.67 320.04,113.67 D40.10
LA
  Top 0.381: R43.1 109.22,32.38 107.95,31.11 107.95,14.61 104.14,10.79 B40.18 104.78,10.16 104.78,10.79 113.03,19.05 113.03,25.4 114.3,26.67 IC2.14
LEFT  (via drill 0.61)  (1 unrouted)
  Top 0.381: IC8.9 149.86,130.81 149.86,128.91 151.13,127.64 151.13,114.94 158.12,107.95 167.64,107.95 167.64,107.31 SV2.1 | v200.66,108.58 200.66,105.41 IC9.14
  Bottom 0.381: v200.66,108.58 182.88,108.58 180.97,106.68 SV1.1
LINK
  Top 0.381: IC4.3 53.34,123.19 55.88,120.65 55.88,114.94 57.15,113.67 C40.28
LSCK  (1 unrouted)
  Top 0.381: SV2.3 167.64,104.78 168.91,106.05 168.91,111.76 151.13,129.54 151.13,133.35 150.5,133.99 148.59,133.99 148.59,130.81 147.96,130.18 144.78,130.18 144.78,130.81 IC8.11 | IC19.1 310.51,12.06 311.79,12.06 IC19.2 313.06,13.34 318.77,19.05 318.77,26.04 326.39,33.66 326.39,127.64 327.02,128.27 327.02,132.72 325.75,133.99 320.04,133.99 320.04,133.35 IC13.11 | IC11.11 233.68,102.87 233.68,99.06 232.41,97.79 232.41,95.25 233.04,94.61 240.03,94.61 240.03,107.31 238.76,108.58 238.76,119.38 234.95,123.19 234.95,125.73 233.68,127 233.68,130.81 IC12.11
  Bottom 0.381: 142.88,106.05 121.28,106.05 120.02,104.78 IC5.11 | 142.88,106.05 144.15,104.78 IC7.11 | 142.88,106.05 150.5,106.05 151.13,105.41 165.74,105.41 167,104.14 SV2.3 | IC8.11 144.15,131.44 142.88,130.18 121.28,130.18 120.02,131.44 IC6.11 118.75,131.44 116.84,129.54 58.42,129.54 | 58.42,129.54 60.33,131.44 IC4.11 | 58.42,129.54 57.78,128.91 31.75,128.91 31.75,133.35 32.38,133.99 33.66,133.99 34.92,132.72 IC1.11 | 210.19,106.05 208.91,104.78 IC9.11 | 210.19,106.05 231.78,106.05 233.04,104.78 IC11.11 | 210.19,106.05 194.94,106.05 193.04,104.14 180.97,104.14 SV1.3 | IC17.16 287.65,19.68 288.93,18.41 290.19,18.41 291.46,19.68 IC17.14 292.1,19.05 293.37,19.05 293.37,11.43 294,10.79 307.98,10.79 309.25,12.06 IC19.1 | IC16.11 347.35,131.44 346.07,130.18 321.94,130.18 320.68,131.44 IC13.11 319.4,131.44 317.5,129.54 231.14,129.54 | 231.14,129.54 233.04,131.44 IC12.11 | 231.14,129.54 230.5,128.91 204.47,128.91 204.47,133.35 205.1,133.99 206.38,133.99 207.65,132.72 IC10.11
LSER  (via drill 0.61)  (1 unrouted)
  Top 0.381: v280.67,58.42 280.67,22.86 281.94,21.59 IC17.18
  Bottom 0.381: v280.67,58.42 219.07,58.42 180.97,96.52 SV1.9 | IC1.14 28.57,132.72 32.38,136.53 168.91,136.53 171.45,133.99 171.45,97.16 167.64,97.16 SV2.9
MA0
  Top 0.381: IC5.1 106.68,97.79 107.95,99.06 107.95,109.86 110.49,112.39 110.49,113.67 109.22,114.94 E40.3
MA1  (via drill 0.61)
  Top 0.381: v118.11,109.86 118.11,99.06 119.38,97.79 IC5.6
  Bottom 0.381: v118.11,109.86 114.94,113.03 E40.8
MA2
  Top 0.381: IC6.3 111.76,123.19 116.84,118.11 116.84,117.47 118.11,116.2 118.11,114.94 118.75,114.3 121.28,114.3 121.28,115.57 E40.13
MA3
  Top 0.381: IC7.15 134.62,105.41 133.35,106.68 133.35,111.12 132.08,112.39 E40.22
MA4
  Top 0.381: IC7.5 142.24,97.79 140.97,99.06 140.97,113.67 139.7,114.94 E40.27
MA5
  Bottom 0.381: IC8.2 134.62,123.19 134.62,118.75 135.89,118.75 138.43,116.2 138.43,110.49 144.15,110.49 144.78,111.12 144.78,112.39 E40.32
MA6
  Top 0.381: IC9.1 195.58,97.79 196.85,99.06 196.85,109.86 199.39,112.39 199.39,113.67 198.12,114.94 F40.3
MA7
  Top 0.381: IC9.6 208.28,97.79 208.28,101.6 207.01,102.87 207.01,116.2 206.38,116.84 204.47,116.84 204.47,114.94 203.2,113.67 F40.8
MA8
  Bottom 0.381: IC10.3 201.29,123.83 208.28,116.84 208.91,116.84 210.19,115.57 F40.13
MA9
  Top 0.381: IC11.15 223.52,105.41 220.98,107.95 220.98,112.39 F40.22
MA10
  Top 0.381: IC11.5 231.14,97.79 229.87,99.06 229.87,113.67 228.6,114.94 F40.27
MA11
  Bottom 0.381: IC12.2 223.52,123.19 223.52,116.84 224.16,116.84 224.79,116.2 224.79,111.76 231.78,111.76 233.04,113.03 F40.32
MASTER-RESET#  (via drill 0.61)
  Top 0.381: IDE.1 297.18,130.18 297.18,117.47 295.91,116.2 295.91,114.94 297.18,113.67 SLOT1.1 297.18,112.39 297.18,99.69 295.91,98.42 295.91,97.16 297.18,95.89 SLOT2.1 | v302.89,9.53 306.07,12.7 306.07,24.13 308.61,26.67 v308.61,95.25
  Bottom 0.381: v302.89,9.53 285.12,9.53 282.57,12.06 IC17.3 | v308.61,95.25 297.81,95.25 SLOT2.1
MB0
  Top 0.381: IC5.2 109.22,97.79 113.03,101.6 113.03,113.67 111.76,114.94 E40.5
MB1  (via drill 0.61)
  Top 0.381: v101.6,107.31 101.6,93.34 120.65,93.34 121.92,94.61 121.92,95.25 IC5.7
  Bottom 0.381: v101.6,107.31 106.05,111.76 109.86,111.76 111.12,113.03 E40.6
MB2
  Bottom 0.381: IC6.4 114.94,123.83 120.65,118.11 131.44,118.11 133.35,116.2 133.35,114.3 126.36,114.3 125.09,115.57 E40.15
MB3
  Top 0.381: IC7.1 132.08,97.79 125.73,104.14 125.73,111.12 124.46,112.39 E40.16
MB4  (via drill 0.61)
  Top 0.381: v146.05,108.58 146.05,99.06 144.78,97.79 IC7.6
  Bottom 0.381: v146.05,108.58 146.05,116.84 142.88,116.84 142.24,116.2 E40.29
MB5  (via drill 0.61)
  Top 0.381: v140.97,121.92 140.97,114.94 142.24,113.67 E40.30
  Bottom 0.381: v140.97,121.92 139.7,121.92 137.79,123.83 IC8.3
MB6
  Top 0.381: IC9.2 198.12,97.79 199.39,99.06 199.39,109.86 201.93,112.39 201.93,113.67 200.66,114.94 F40.5
MB7  (via drill 0.61)
  Top 0.381: v209.55,108.58 209.55,99.06 210.82,97.79 IC9.7
  Bottom 0.381: v209.55,108.58 206.38,111.76 202.56,111.76 201.29,113.03 F40.6
MB8
  Bottom 0.381: IC10.4 203.84,123.83 210.82,116.84 211.46,116.84 212.72,115.57 F40.15
MB9  (via drill 0.61)
  Top 0.381: v218.44,99.06 217.17,100.33 v217.17,111.12
  Bottom 0.381: v218.44,99.06 220.34,97.16 IC11.1 | v217.17,111.12 216.53,111.76 215.26,111.76 214,113.03 F40.16
MB10  (via drill 0.61)
  Top 0.381: v234.95,111.76 234.95,99.06 233.68,97.79 IC11.6
  Bottom 0.381: v234.95,111.76 234.95,114.3 233.04,114.3 231.78,115.57 F40.29
MB11
  Top 0.381: IC12.3 226.06,125.73 222.25,129.54 222.25,133.35 222.88,133.99 224.79,133.99 224.79,130.81 229.87,125.73 229.87,114.94 231.14,113.67 F40.30
MQ0
  Top 0.381: IC5.4 114.94,95.89 116.2,94.61 120.65,94.61 120.65,109.86 118.11,112.39 118.11,113.67 116.84,114.94 E40.9
MQ1
  Top 0.381: IC6.1 106.68,123.19 105.41,121.92 105.41,114.94 106.68,113.67 E40.2
MQ2
  Bottom 0.381: IC6.6 120.02,123.83 124.46,119.38 131.44,119.38 134.62,116.2 E40.23
MQ3  (via drill 0.61)
  Top 0.381: v127,109.86 127,104.14 133.35,97.79 133.35,94.61 135.25,94.61 136.53,95.89 IC7.3
  Bottom 0.381: v127,109.86 126.36,110.49 122.56,110.49 120.02,113.03 E40.12
MQ4  (via drill 0.61)
  Top 0.381: v135.89,126.36 135.89,129.54 134.62,130.81 IC8.15
  Bottom 0.381: v135.89,126.36 142.88,126.36 143.51,125.73 143.51,119.38 147.96,119.38 149.86,117.47 149.86,115.57 147.96,115.57 E40.33
MQ5  (via drill 0.61)
  Top 0.381: v137.16,120.65 135.89,119.38 135.89,114.94 137.16,113.67 E40.26
  Bottom 0.381: v137.16,120.65 142.24,120.65 142.24,123.19 IC8.5
MQ6
  Top 0.381: IC9.4 202.56,97.16 201.93,97.79 201.93,109.86 204.47,112.39 204.47,113.67 205.74,114.94 F40.9
MQ7
  Top 0.381: IC10.1 195.58,123.19 194.31,121.92 194.31,114.94 195.58,113.67 F40.2
MQ8
  Bottom 0.381: IC10.6 208.91,123.83 215.9,116.84 221.62,116.84 222.88,115.57 F40.23
MQ9  (via drill 0.61)
  Top 0.381: v219.71,108.58 219.71,94.61 224.16,94.61 225.43,95.89 IC11.3
  Bottom 0.381: v219.71,108.58 213.36,108.58 208.91,113.03 F40.12
MQ10  (via drill 0.61)
  Top 0.381: v227.33,119.38 227.33,127 223.52,130.81 IC12.15
  Bottom 0.381: v227.33,119.38 229.87,116.84 234.31,116.84 235.59,115.57 F40.33
MQ11
  Bottom 0.381: IC12.5 230.5,123.83 227.33,120.65 226.69,120.65 226.06,120.02 226.06,116.84 226.69,116.84 227.33,116.2 227.33,113.67 226.06,113.67 F40.26
N$1
  Bottom 0.381: IC14.9 41.27,28.57 42.55,29.84 64.14,29.84 65.41,28.57 IC15.10
N$2
  Bottom 0.381: IC15.9 69.22,28.57 70.48,29.84 122.56,29.84 123.83,28.57 IC2.10
N$3
  Bottom 0.381: IC18.10 97.16,27.3 99.06,25.4 124.46,25.4 126.36,27.3 IC2.9
N$4  (via drill 0.61)
  Top 0.381: v124.46,107.31 124.46,105.41 IC5.9 | v104.14,107.31 104.14,123.83 105.41,125.09 105.41,128.27 107.95,130.81 107.95,133.35 108.58,133.99 111.76,133.99 111.76,133.35 IC6.14
  Bottom 0.381: v104.14,107.31 v124.46,107.31
N$5
  Top 0.381: IC3.10 241.3,21.59 241.3,27.3 R3.2
N$6
  Top 0.381: IC3.11 238.76,21.59 238.76,24.77 R1.2
N$7  (via drill 0.61)
  Top 0.381: v245.11,49.53 245.11,22.86 243.84,21.59 IC3.9 | v334.01,49.53 336.55,46.99 336.55,6.99 337.82,5.71 R2.2
  Bottom 0.381: v245.11,49.53 v334.01,49.53
N$8
  Top 0.381: C1.2 228.6,8.26 228.6,11.43 IC3.2
N$9
  Top 0.381: C2.2 231.14,5.71 231.14,11.43 IC3.3
N$10
  Bottom 0.381: IC1.9 41.27,132.72 42.55,133.99 51.44,133.99 52.7,132.72 IC4.14
N$11
  Top 0.381: C2.1 226.06,5.71 226.06,11.43 IC3.1
N$12
  Top 0.381: C4.1 241.3,5.71 240.03,6.99 240.03,10.16 238.76,11.43 IC3.6
N$13  (via drill 0.61)
  Top 0.381: v148.59,116.84 148.59,106.68 149.86,105.41 IC7.9 | v138.43,118.11 138.43,129.54 137.16,130.81 IC8.14
  Bottom 0.381: v148.59,116.84 147.32,118.11 v138.43,118.11
N$14  (via drill 0.61)
  Top 0.381: v129.54,131.44 133.35,127.64 133.35,114.94 133.99,114.3 135.25,114.3 135.89,113.67 135.89,109.86 137.16,108.58 137.16,105.41 IC7.14
  Bottom 0.381: v129.54,131.44 125.09,131.44 IC6.9
N$15  (via drill 0.61)
  Top 0.381: v232.41,102.23 232.41,125.73 226.69,131.44 IC12.14
  Bottom 0.381: v232.41,102.23 236.85,102.23 238.12,103.5 IC11.9
N$16  (via drill 0.61)
  Top 0.381: v219.07,131.44 224.79,125.73 224.79,112.39 226.06,111.12 226.06,105.41 IC11.14
  Bottom 0.381: v219.07,131.44 214,131.44 IC10.9
N$17  (via drill 0.61)
  Top 0.381: v333.38,132.72 337.19,136.53 340.36,136.53 340.36,133.35 IC16.14
  Bottom 0.381: v333.38,132.72 325.75,132.72 IC13.9
N$18
  Top 0.381: C3.1 233.68,8.26 233.68,11.43 IC3.4
N$19
  Top 0.381: IC9.9 213.36,102.87 214.63,101.6 214.63,95.25 212.72,93.34 190.5,93.34 190.5,121.28 194.31,125.09 194.31,128.27 196.85,130.81 196.85,133.35 197.49,133.99 200.66,133.99 200.66,133.35 IC10.14
N$20
  Top 0.381: C3.2 238.76,8.26 236.22,10.79 236.22,11.43 IC3.5
N$21  (via drill 0.61)
  Top 0.381: v90.81,106.05 66.04,130.81 IC4.9
  Bottom 0.381: v90.81,106.05 109.86,106.05 111.12,104.78 IC5.14
N$22  (via drill 0.61)
  Top 0.381: v339.09,15.88 344.17,20.95 344.17,79.38 358.14,93.34 358.14,125.73 353.06,130.81 IC16.9
  Bottom 0.381: v339.09,15.88 323.21,15.88 320.68,13.34 IC19.5
N$23  (via drill 0.61)
  Top 0.381: v237.49,122.56 237.49,129.54 238.76,130.81 IC12.9 | v309.88,119.38 311.15,120.65 311.15,129.54 312.42,130.81 IC13.14
  Bottom 0.381: v237.49,122.56 239.4,120.65 298.45,120.65 299.72,119.38 v309.88,119.38
N$27
  Top 0.381: IC19.3 315.6,12.06 316.87,12.06 IC19.4
N$28
  Top 0.381: R11.1 289.56,4.45 292.1,6.99 292.1,11.43 IC17.7
N$29
  Bottom 0.381: R21.2 261.62,106.05 261.62,111.76 260.99,111.76 259.71,113.03 SLOT1.31
N$30
  Top 0.381: R22.2 259.08,104.78 257.81,103.5 257.81,97.16 259.08,95.89 SLOT2.31
N$31
  Top 0.381: R23.2 271.78,27.3 266.7,22.23 266.7,18.41 R20.2 266.06,17.78 264.8,17.78 C5.1 264.16,17.14 264.16,16.51 RESET.2 263.52,13.97 263.52,3.81 RESET.1
  Bottom 0.381: IC17.17 283.85,19.68 281.94,17.78 267.33,17.78 R20.2
N$52  (via drill 0.61)
  Top 0.381: v311.15,91.44 313.69,93.98 313.69,109.86 316.23,112.39 v316.23,118.11 | v262.25,124.46 259.08,127.64 259.08,130.18 IDE.31
  Bottom 0.381: v311.15,91.44 305.44,91.44 R16.2 | v316.23,118.11 313.69,120.65 307.98,120.65 304.17,124.46 v262.25,124.46
N$53  (via drill 0.61)
  Top 0.381: v267.97,136.53 265.43,133.99 265.43,132.72 264.16,131.44 IDE.27
  Bottom 0.381: v267.97,136.53 356.87,136.53 356.87,115.57 353.06,111.76 349.88,111.76 333.38,95.25 314.32,95.25 313.06,93.98 305.44,93.98 R15.2
N$54  (via drill 0.61)
  Top 0.381: v306.07,120.65 306.07,98.42 304.8,97.16 R14.2 | v267.97,123.19 266.7,124.46 266.7,130.18 IDE.25
  Bottom 0.381: v306.07,120.65 303.53,123.19 v267.97,123.19
N$55  (via drill 0.61)
  Top 0.381: v300.36,120.65 303.53,117.47 303.53,100.97 304.8,99.69 R13.2 | v270.51,121.92 269.24,123.19 269.24,130.18 IDE.23
  Bottom 0.381: v300.36,120.65 299.08,121.92 v270.51,121.92
N$56  (via drill 0.61)
  Top 0.381: v262.89,111.76 262.89,120.02 263.52,120.65 271.78,120.65 271.78,130.18 IDE.21
  Bottom 0.381: v262.89,111.76 271.78,102.87 302.89,102.87 304.17,101.6 R12.2
OPR  (via drill 0.61)
  Top 0.381: v327.66,120.02 328.93,118.75 328.93,114.94 327.66,113.67 D40.16
  Bottom 0.381: v327.66,120.02 327.02,120.02 323.21,123.83 IC13.7
PAUSE
  Bottom 0.381: IC16.1 335.92,125.09 337.19,126.36 338.45,126.36 339.09,125.73 339.09,118.75 349.25,118.75 351.79,116.2 351.79,114.3 349.88,114.3 348.62,115.57 D40.31
PB-A0  (via drill 0.61)
  Top 0.381: v244.47,92.08 244.47,93.34 241.94,93.34 240.03,91.44 240.03,81.92 236.22,78.11 236.22,38.73 XESS.57 | SLOT2.35 254,95.89 252.73,97.16 252.73,111.12 254,112.39 SLOT1.35 254,113.67 252.73,114.94 252.73,128.91 254,130.18 IDE.35
  Bottom 0.381: v244.47,92.08 246.38,93.98 252.09,93.98 253.37,95.25 SLOT2.35
PB-A1  (via drill 0.61)
  Top 0.381: IDE.33 256.54,130.18 257.81,128.91 257.81,114.94 256.54,113.67 SLOT1.33 256.54,112.39 256.54,99.69 255.27,98.42 255.27,97.16 256.54,95.89 SLOT2.33 256.54,94.61 257.81,93.34 257.81,81.92 257.18,81.28 257.18,45.09 v256.54,44.45
  Bottom 0.381: v256.54,44.45 245.75,44.45 239.4,38.1 XESS.56
PB-A2
  Top 0.381: XESS.51 252.09,38.1 253.37,36.83 255.27,36.83 255.27,95.89 254,97.16 SLOT2.36 254,98.42 255.27,99.69 255.27,113.67 | 255.27,113.67 254,114.94 SLOT1.36 | 255.27,113.67 255.27,131.44 254,132.72 IDE.36
PB-A3  (via drill 0.61)
  Top 0.381: SLOT2.38 251.46,98.42 251.46,111.12 252.73,112.39 252.73,113.67 251.46,114.94 SLOT1.38 | v242.57,92.08 242.57,81.92 246.38,78.11 246.38,46.35 254,38.73 XESS.50
  Bottom 0.381: v242.57,92.08 247.01,96.52 249.56,96.52 250.82,97.79 SLOT2.38
PB-A4  (via drill 0.61)
  Top 0.381: 247.65,90.17 248.92,91.44 248.92,94.61 SLOT2.39 | v247.01,89.53 247.65,90.17 | 247.65,90.17 247.65,111.12 248.92,112.39 SLOT1.39
  Bottom 0.381: v247.01,89.53 243.84,89.53 236.85,82.55 XESS.70
PB-D0  (via drill 0.61)
  Top 0.381: IDE.17 276.86,130.18 275.59,128.91 275.59,114.94 276.86,113.67 SLOT1.17 276.86,112.39 276.86,99.69 275.59,98.42 275.59,97.16 276.86,95.89 SLOT2.17 276.86,94.61 276.86,87.63 v273.69,84.45
  Bottom 0.381: v273.69,84.45 241.3,84.45 239.4,82.55 XESS.71
PB-D1
  Top 0.381: IDE.15 279.4,130.18 279.4,117.47 278.13,116.2 278.13,114.94 279.4,113.67 SLOT1.15 279.4,112.39 279.4,99.69 278.13,98.42 278.13,93.34 | 278.13,93.34 278.13,81.92 279.4,80.64 279.4,38.73 XESS.40 | 278.13,93.34 279.4,94.61 SLOT2.15
PB-D2
  Top 0.381: IDE.13 281.94,130.18 281.94,117.47 280.67,116.2 280.67,114.94 281.94,113.67 SLOT1.13 281.94,112.39 281.94,99.69 280.67,98.42 280.67,97.16 281.94,95.89 SLOT2.13 281.94,94.61 281.94,85.72 280.67,84.45 280.67,81.92 281.94,80.64 281.94,38.73 XESS.39
PB-D3
  Top 0.381: IDE.11 284.48,130.18 284.48,117.47 283.21,116.2 283.21,114.94 284.48,113.67 SLOT1.11 284.48,112.39 284.48,99.69 283.21,98.42 283.21,97.16 284.48,95.89 SLOT2.11 284.48,94.61 284.48,84.45 283.21,83.19 283.21,40.01 284.48,38.73 XESS.38
PB-D4  (via drill 0.61)
  Top 0.381: SLOT2.9 287.02,95.89 285.75,97.16 285.75,98.42 287.02,99.69 287.02,112.39 SLOT1.9 287.02,113.67 285.75,114.94 285.75,116.2 287.02,117.47 287.02,130.18 IDE.9 | v304.8,44.45 306.07,45.72 306.07,97.16 307.34,98.42 v307.34,111.76
  Bottom 0.381: v304.8,44.45 299.08,44.45 292.74,38.1 XESS.35 | v307.34,111.76 288.93,111.76 287.65,113.03 SLOT1.9
PB-D5  (via drill 0.61)
  Top 0.381: IDE.7 289.56,130.18 289.56,117.47 288.29,116.2 288.29,114.94 289.56,113.67 SLOT1.7 289.56,112.39 289.56,99.69 288.29,98.42 288.29,97.16 289.56,95.89 SLOT2.7 289.56,94.61 290.83,93.34 v290.83,87.63 | v261.62,85.72 261.62,83.19 XESS.80
  Bottom 0.381: v261.62,85.72 263.52,87.63 v290.83,87.63
PB-D6  (via drill 0.61)
  Top 0.381: v285.75,74.93 288.29,77.47 v288.29,93.34 | 290.83,111.12 292.1,112.39 SLOT1.5 | 290.83,111.12 290.83,97.16 292.1,95.89 SLOT2.5 | 290.83,111.12 290.83,116.2 292.1,117.47 292.1,130.18 IDE.5
  Bottom 0.381: v285.75,74.93 272.42,74.93 264.8,82.55 XESS.81 | v288.29,93.34 288.93,93.98 290.19,93.98 291.46,95.25 SLOT2.5
PB-D7
  Top 0.381: XESS.10 297.18,83.19 297.18,92.08 294.64,94.61 SLOT2.3 294.64,95.89 293.37,97.16 293.37,109.22 294.64,110.49 294.64,112.39 SLOT1.3 294.64,113.67 293.37,114.94 293.37,116.2 294.64,117.47 294.64,130.18 IDE.3
PB-D8  (via drill 0.61)
  Top 0.381: v321.31,96.52 321.31,36.83 314.32,36.83 313.06,38.1 XESS.27 | SLOT2.4 294.64,98.42 295.91,99.69 295.91,113.67 294.64,114.94 SLOT1.4 294.64,116.2 295.91,117.47 295.91,131.44 294.64,132.72 IDE.4
  Bottom 0.381: v321.31,96.52 320.04,97.79 300.99,97.79 299.72,96.52 296.55,96.52 295.27,97.79 SLOT2.4
PB-D9  (via drill 0.61)
  Top 0.381: IDE.6 292.1,132.72 293.37,131.44 293.37,117.47 292.1,116.2 SLOT1.6 292.1,114.94 293.37,113.67 293.37,110.49 292.1,109.22 292.1,98.42 SLOT2.6 | v316.23,90.17 316.23,81.92 314.96,80.64 314.96,43.81 309.88,38.73 XESS.28
  Bottom 0.381: v316.23,90.17 316.23,92.71 295.27,92.71 293.37,94.61 293.37,97.16 292.1,97.16 SLOT2.6
PB-D10  (via drill 0.61)
  Top 0.381: SLOT1.8 289.56,116.2 290.83,117.47 290.83,131.44 289.56,132.72 IDE.8 | v298.45,41.91 298.45,96.52 299.72,97.79 v299.72,98.42 299.72,99.69 300.36,100.33 v300.36,116.84
  Bottom 0.381: v298.45,41.91 302.89,41.91 306.7,38.1 XESS.29 | v299.72,98.42 299.08,99.06 291.46,99.06 290.19,97.79 SLOT2.8 | v300.36,116.84 291.46,116.84 290.19,115.57 SLOT1.8
PB-D11  (via drill 0.61)
  Top 0.381: v300.99,99.06 300.99,81.92 299.72,80.64 299.72,38.73 XESS.32 | SLOT2.10 287.02,98.42 288.29,99.69 288.29,113.67 287.02,114.94 SLOT1.10 287.02,116.2 288.29,117.47 288.29,131.44 287.02,132.72 IDE.10
  Bottom 0.381: v300.99,99.06 299.72,100.33 290.19,100.33 287.65,97.79 SLOT2.10
PB-D12  (via drill 0.61)
  Top 0.381: v295.91,85.09 295.91,40.01 297.18,38.73 XESS.33 | v283.21,85.09 v283.21,93.98 | SLOT2.12 284.48,98.42 285.75,99.69 285.75,113.67 284.48,114.94 SLOT1.12 284.48,116.2 285.75,117.47 285.75,131.44 284.48,132.72 IDE.12
  Bottom 0.381: v295.91,85.09 v283.21,85.09 | v283.21,93.98 283.21,97.79 283.85,97.79 SLOT2.12
PB-D13  (via drill 0.61)
  Top 0.381: v293.37,86.36 293.37,40.01 294.64,38.73 XESS.34 | v280.67,86.36 v280.67,93.98 | SLOT2.14 281.94,98.42 283.21,99.69 283.21,113.67 281.94,114.94 SLOT1.14 281.94,116.2 283.21,117.47 283.21,131.44 281.94,132.72 IDE.14
  Bottom 0.381: v293.37,86.36 v280.67,86.36 | v280.67,93.98 280.67,97.79 281.31,97.79 SLOT2.14
PB-D14  (via drill 0.61)
  Top 0.381: v289.56,90.17 289.56,87 290.83,85.72 290.83,40.01 289.56,38.73 XESS.36 | SLOT2.16 279.4,98.42 280.67,99.69 280.67,113.67 279.4,114.94 SLOT1.16 279.4,116.2 280.67,117.47 280.67,131.44 279.4,132.72 IDE.16
  Bottom 0.381: v289.56,90.17 287.02,92.71 280.04,92.71 278.13,94.61 278.13,97.79 278.76,97.79 SLOT2.16
PB-D15  (via drill 0.61)
  Top 0.381: v285.75,93.98 285.75,81.92 284.48,80.64 284.48,69.22 287.02,66.67 287.02,38.73 XESS.37 | SLOT2.18 276.86,98.42 278.13,99.69 278.13,113.67 276.86,114.94 SLOT1.18 276.86,116.2 278.13,117.47 278.13,131.44 276.86,132.72 IDE.18
  Bottom 0.381: v285.75,93.98 285.75,99.06 277.5,99.06 276.86,98.42 SLOT2.18
PB-RD#  (via drill 0.61)
  Top 0.381: v316.23,107.95 316.23,98.42 314.96,97.16 R14.1 | v258.44,46.99 266.7,55.24 266.7,80.64 265.43,81.92 265.43,93.34 | 265.43,93.34 266.7,94.61 SLOT2.25 | 265.43,93.34 265.43,111.12 266.7,112.39 SLOT1.25
  Bottom 0.381: v316.23,107.95 313.69,110.49 269.88,110.49 267.33,113.03 SLOT1.25 | v258.44,46.99 235.59,46.99 226.69,38.1 XESS.61
PB-WR#  (via drill 0.61)
  Top 0.381: v270.51,50.8 270.51,93.34 269.24,94.61 SLOT2.23 269.24,95.89 267.97,97.16 267.97,111.12 269.24,112.39 SLOT1.23
  Bottom 0.381: R13.1 314.96,99.69 316.23,100.97 316.23,105.41 273.69,105.41 267.33,111.76 266.06,111.76 265.43,112.39 265.43,114.3 267.33,114.3 268.61,113.03 SLOT1.23 | v270.51,50.8 235.59,50.8 223.52,38.73 XESS.62
PC0
  Top 0.381: IC5.15 109.22,102.87 109.22,99.06 107.95,97.79 107.95,95.25 107.31,94.61 105.41,94.61 105.41,109.86 107.95,112.39 107.95,113.67 106.68,114.94 E40.1
PC1
  Top 0.381: IC5.5 116.84,97.79 115.57,99.06 115.57,111.12 116.84,112.39 E40.10
PC2
  Top 0.381: IC6.2 109.86,125.09 111.12,126.36 118.11,126.36 118.11,117.47 119.38,116.2 E40.11
PC3
  Bottom 0.381: IC6.7 122.56,123.83 125.73,120.65 131.44,120.65 135.89,116.2 135.89,113.67 134.62,113.67 E40.24
PC4
  Top 0.381: IC7.4 139.7,97.79 138.43,99.06 138.43,113.67 137.16,114.94 E40.25
PC5
  Bottom 0.381: IC8.1 132.72,125.09 135.25,127.64 144.15,127.64 146.05,125.73 146.05,120.65 147.96,120.65 151.13,117.47 151.13,113.67 147.32,113.67 E40.34
PC6  (via drill 0.61)
  Top 0.381: v195.58,101.6 194.31,102.87 194.31,109.86 196.85,112.39 196.85,113.67 195.58,114.94 F40.1
  Bottom 0.381: v195.58,101.6 197.49,103.5 IC9.15
PC7
  Top 0.381: IC9.5 205.74,97.79 204.47,99.06 204.47,111.12 205.74,112.39 F40.10
PC8
  Bottom 0.381: IC10.2 198.75,123.83 205.74,116.84 206.38,116.84 207.65,115.57 F40.11
PC9  (via drill 0.61)
  Top 0.381: v212.09,111.76 212.09,121.92 210.82,123.19 IC10.7
  Bottom 0.381: v212.09,111.76 214,109.86 219.71,109.86 222.88,113.03 F40.24
PC10
  Top 0.381: IC11.4 228.6,97.79 227.33,99.06 227.33,113.67 226.06,114.94 F40.25
PC11
  Bottom 0.381: IC12.1 221.62,125.09 222.88,126.36 234.31,126.36 234.95,125.73 234.95,117.47 236.22,117.47 237.49,116.2 237.49,113.67 236.22,113.67 F40.34
RCK  (via drill 0.61)  (1 unrouted)
  Top 0.381: IC9.12 205.74,102.87 207.01,101.6 v207.01,94.61 211.46,94.61 212.09,95.25 212.09,105.41 214.63,107.95 214.63,133.99 207.65,133.99 206.38,132.72 IC10.12 | IC19.6 322.58,11.43 323.21,10.79 323.21,5.08 325.12,3.17 331.47,3.17 331.47,76.83 347.98,93.34 347.98,102.87 339.09,111.76 339.09,128.27 341.63,130.81 341.63,133.35 342.26,133.99 345.44,133.99 345.44,133.35 IC16.12 | v128.27,104.78 128.27,133.99 125.73,136.53 116.84,136.53 116.84,133.35 IC6.12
